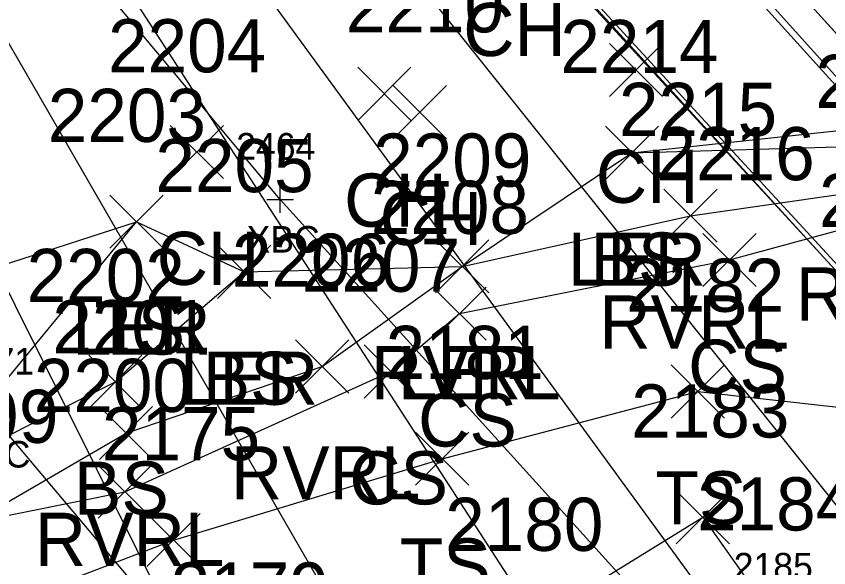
# Model space of a CAD drawing. Extents: x 1504228 to 1506103, y 437717 to 440106.
# Drawn here: x 1505234.96 to 1505265.52, y 438165.45 to 438186.2 of the extents above; entities that cross this region are included whole.
import ezdxf

# ---------------------------------------------------------------- set-up
doc = ezdxf.new("R2010")
doc.units = 0
for name, color, linetype in [('B_A', 7, 'Continuous'), ('B_I', 7, 'Continuous'), ('B_TIC', 7, 'Continuous'), ('BB', 7, 'Continuous'), ('BDC', 7, 'Continuous'), ('BELB', 7, 'Continuous'), ('BF', 7, 'Continuous'), ('BR', 7, 'Continuous'), ('L_A', 7, 'Continuous'), ('L_I', 7, 'Continuous'), ('L_TIC', 7, 'Continuous'), ('LARO', 7, 'Continuous'), ('LAWE', 7, 'Continuous'), ('LELB', 7, 'Continuous')]:
    doc.layers.add(name, color=color, linetype=linetype)

msp = doc.modelspace()

# ---------------------------------------------------------------- linework, layer by layer
at = {"layer": 'B_TIC'}
msp.add_line((1505244.887, 438179.311), (1505244.963, 438179.311), dxfattribs=at)
for points in [[(1505244.884, 438178.811), (1505244.884, 438179.811)], [(1505244.384, 438179.311), (1505245.384, 438179.311)]]:
    msp.add_lwpolyline(points, dxfattribs=at)
at = {"layer": 'BB'}
for points in [[(1505279.36, 438168.588), (1505247.631, 438203.673)], [(1505274.859, 438166.697), (1505243.111, 438201.465)], [(1505269.01, 438163.806), (1505239.92, 438200.195)], [(1505263.198, 438161.205), (1505236.12, 438198.358)], [(1505257.379, 438159.077), (1505232.798, 438197.013)], [(1505251.441, 438156.129), (1505228.857, 438195.264)], [(1505245.599, 438153.876), (1505225.746, 438193.733)]]:
    msp.add_lwpolyline(points, dxfattribs=at)
at = {"layer": 'BDC'}
msp.add_lwpolyline([(1505211.925, 438243.921), (1505227.096, 438222.88), (1505239.823, 438206.409), (1505253.849, 438189.887), (1505268.071, 438174.436), (1505276.686, 438165.513)], dxfattribs=at)
at = {"layer": 'BELB'}
for points in [[(1505211.812, 438243.704), (1505226.972, 438222.631), (1505239.63, 438206.209), (1505253.732, 438189.745), (1505267.938, 438174.29), (1505276.516, 438165.316)], [(1505262.808, 438159.474), (1505244.884, 438179.311), (1505229.042, 438198.247), (1505213.306, 438219.16), (1505200.113, 438237.757)], [(1505189.093, 438232.07), (1505202.074, 438213.317), (1505217.089, 438192.519), (1505234.002, 438171.224), (1505249.231, 438153.134)]]:
    msp.add_lwpolyline(points, dxfattribs=at)
at = {"layer": 'BF'}
for points in [[(1505211.925, 438243.921), (1505216.347, 438245.376), (1505218.618, 438242.78), (1505219.411, 438243.379), (1505231.883, 438226.243), (1505244.785, 438210.059), (1505258.149, 438194.034), (1505272.082, 438178.605), (1505279.641, 438170.867), (1505278.911, 438170.024), (1505281.091, 438167.856), (1505276.686, 438165.513)], [(1505219.325, 438243.288), (1505231.877, 438226.273), (1505244.695, 438209.964), (1505258.118, 438194.019), (1505272.126, 438178.595), (1505280.957, 438169.659)]]:
    msp.add_lwpolyline(points, dxfattribs=at)
at = {"layer": 'BR'}
msp.add_lwpolyline([(1505218.618, 438242.78), (1505231.125, 438225.649), (1505244.017, 438209.29), (1505257.36, 438193.318), (1505271.307, 438177.817), (1505278.911, 438170.024)], dxfattribs=at)
at = {"layer": 'L_TIC'}
for points in [[(1505257.268, 438183.183), (1505259.268, 438185.183)], [(1505259.268, 438183.183), (1505257.268, 438185.183)], [(1505247.799, 438182.285), (1505249.799, 438184.285)], [(1505249.799, 438182.285), (1505247.799, 438184.285)], [(1505249.135, 438181.597), (1505251.135, 438183.597)], [(1505251.135, 438181.597), (1505249.135, 438183.597)], [(1505240.748, 438180.094), (1505242.748, 438182.094)], [(1505242.748, 438180.094), (1505240.748, 438182.094)], [(1505257.116, 438180.066), (1505259.116, 438182.066)], [(1505259.116, 438180.066), (1505257.116, 438182.066)], [(1505257.116, 438180.066), (1505259.116, 438182.066)], [(1505259.116, 438180.066), (1505257.116, 438182.066)], [(1505259.319, 438177.7), (1505261.319, 438179.7)], [(1505261.319, 438177.7), (1505259.319, 438179.7)], [(1505238.482, 438177.474), (1505240.482, 438179.474)], [(1505240.482, 438177.474), (1505238.482, 438179.474)], [(1505238.482, 438177.474), (1505240.482, 438179.474)], [(1505240.482, 438177.474), (1505238.482, 438179.474)], [(1505260.788, 438176.035), (1505262.788, 438178.035)], [(1505262.788, 438176.035), (1505260.788, 438178.035)], [(1505250.729, 438175.792), (1505252.729, 438177.792)], [(1505252.729, 438175.792), (1505250.729, 438177.792)], [(1505250.729, 438175.792), (1505252.729, 438177.792)], [(1505252.729, 438175.792), (1505250.729, 438177.792)], [(1505242.528, 438175.585), (1505244.528, 438177.585)], [(1505244.528, 438175.585), (1505242.528, 438177.585)], [(1505242.528, 438175.585), (1505244.528, 438177.585)], [(1505244.528, 438175.585), (1505242.528, 438177.585)], [(1505250.629, 438174.015), (1505252.629, 438176.015)], [(1505252.629, 438174.015), (1505250.629, 438176.015)], [(1505245.461, 438172.024), (1505247.461, 438174.024)], [(1505247.461, 438172.024), (1505245.461, 438174.024)], [(1505248.04, 438171.836), (1505250.04, 438173.836)], [(1505250.04, 438171.836), (1505248.04, 438173.836)], [(1505237.686, 438171.451), (1505239.686, 438173.451)], [(1505239.686, 438171.451), (1505237.686, 438173.451)], [(1505259.591, 438171.084), (1505261.591, 438173.084)], [(1505261.591, 438171.084), (1505259.591, 438173.084)], [(1505238.085, 438169.522), (1505240.085, 438171.522)], [(1505240.085, 438169.522), (1505238.085, 438171.522)], [(1505249.977, 438168.557), (1505251.977, 438170.557)], [(1505251.977, 438168.557), (1505249.977, 438170.557)], [(1505238.043, 438167.314), (1505240.043, 438169.314)], [(1505240.043, 438167.314), (1505238.043, 438169.314)], [(1505259.782, 438166.353), (1505261.782, 438168.353)], [(1505261.782, 438166.353), (1505259.782, 438168.353)], [(1505239.87, 438165.496), (1505241.87, 438167.496)], [(1505241.87, 438165.496), (1505239.87, 438167.496)]]:
    msp.add_lwpolyline(points, dxfattribs=at)
at = {"layer": 'LARO'}
msp.add_lwpolyline([(1505225.066, 438161.326), (1505226.248, 438169.057), (1505228.34, 438173.672), (1505225.288, 438173.876), (1505239.482, 438178.474), (1505243.528, 438176.585), (1505251.729, 438176.792), (1505258.116, 438181.066), (1505273.159, 438181.503), (1505274.516, 438179.171), (1505287.419, 438180.921)], dxfattribs=at)
at = {"layer": 'LAWE'}
msp.add_lwpolyline([(1505191.715, 438146.002), (1505202.906, 438148.803), (1505214.791, 438151.569), (1505218.42, 438155.881), (1505225.066, 438161.326), (1505233.297, 438167.151), (1505239.085, 438170.522), (1505246.461, 438173.024), (1505251.729, 438176.792), (1505260.319, 438178.7), (1505267.708, 438179.756), (1505273.159, 438181.503), (1505280.716, 438184.584), (1505293.606, 438188.67), (1505306.287, 438194.997), (1505316.183, 438195.439), (1505329.815, 438205.572), (1505347.823, 438213.433)], dxfattribs=at)
at = {"layer": 'LELB'}
for points in [[(1505258.116, 438181.066), (1505268.339, 438182.172), (1505278.498, 438189.358), (1505293.602, 438192.608), (1505306.445, 438196.96), (1505314.273, 438197.344), (1505329.9, 438207.293), (1505346.396, 438216.217), (1505367.728, 438232.021), (1505378.412, 438248.378), (1505391.234, 438272.553), (1505398.951, 438287.599)], [(1505215.631, 438142.954), (1505216.782, 438152.684), (1505223.21, 438155.651), (1505231.417, 438162.88), (1505240.87, 438166.496), (1505250.977, 438169.557), (1505260.591, 438172.084), (1505271.035, 438170.915), (1505277.265, 438170.598), (1505281.518, 438175.58), (1505287.828, 438178.641), (1505292.056, 438179.708), (1505296.753, 438181.832), (1505306.221, 438188.545)], [(1505233.297, 438167.151), (1505239.043, 438168.314), (1505249.04, 438172.836), (1505251.629, 438175.015), (1505261.788, 438177.035), (1505269.325, 438179.089), (1505274.516, 438179.171), (1505268.419, 438175.277), (1505270.919, 438173.353), (1505279.4, 438176.776), (1505285.106, 438180.489)], [(1505231.587, 438168.903), (1505239.482, 438178.474)], [(1505226.248, 438169.057), (1505231.587, 438168.903), (1505238.686, 438172.451), (1505243.528, 438176.585)], [(1505245.889, 438156.33), (1505243.468, 438160.651), (1505253.871, 438163.088), (1505260.782, 438167.353), (1505263.257, 438163.856)]]:
    msp.add_lwpolyline(points, dxfattribs=at)

# ---------------------------------------------------------------- texts
at = {"layer": 'B_A'}
for p in [(1505243.62, 438177.311), (1505232.738, 438169.224)]:
    msp.add_text('XBC', height=1, dxfattribs=at).set_placement(p)
at = {"layer": 'B_I'}
for s, p in [('2464', (1505243.23, 438180.811)), ('2471', (1505232.655, 438172.724)), ('2185', (1505261.944, 438165.011))]:
    msp.add_text(s, height=1, dxfattribs=at).set_placement(p)
at = {"layer": 'L_A'}
for s, p in [('CH', (1505251.768, 438184.706)), ('CH', (1505256.756, 438179.183)), ('CH', (1505247.287, 438178.285)), ('CH', (1505248.623, 438177.597)), ('CH', (1505240.236, 438176.094)), ('LER', (1505255.698, 438176.066)), ('BS', (1505256.556, 438176.066)), ('RVRL', (1505264.275, 438174.756)), ('RVRL', (1505256.886, 438173.7)), ('LER', (1505237.064, 438173.474)), ('TS', (1505237.891, 438173.474)), ('CS', (1505260.229, 438172.035)), ('RVRL', (1505248.296, 438171.792)), ('LER', (1505249.312, 438171.792)), ('LER', (1505241.111, 438171.585)), ('BS', (1505241.969, 438171.585)), ('CS', (1505250.07, 438170.015)), ('RVRL', (1505243.028, 438168.024)), ('CS', (1505247.481, 438167.836)), ('BS', (1505237.127, 438167.451)), ('TS', (1505259.001, 438167.084)), ('RVRL', (1505235.652, 438165.522)), ('TS', (1505249.387, 438164.557))]:
    msp.add_text(s, height=2, dxfattribs=at).set_placement(p)
at = {"layer": 'L_I'}
for s, p in [('2210', (1505247.355, 438185.597)), ('2204', (1505238.409, 438184.094)), ('2214', (1505255.423, 438184.066)), ('2214', (1505255.423, 438184.066)), ('2218', (1505265.016, 438182.756)), ('2203', (1505236.143, 438181.474)), ('2203', (1505236.143, 438181.474)), ('2215', (1505257.626, 438181.7)), ('2216', (1505259.04, 438180.035)), ('2209', (1505248.383, 438179.792)), ('2209', (1505248.383, 438179.792)), ('2205', (1505240.19, 438179.585)), ('2205', (1505240.19, 438179.585)), ('2229', (1505265.151, 438178.277)), ('2208', (1505248.29, 438178.015)), ('2206', (1505243.067, 438176.024)), ('2207', (1505245.701, 438175.836)), ('2202', (1505235.347, 438175.451)), ('2182', (1505257.898, 438175.084)), ('2201', (1505236.313, 438173.522)), ('2181', (1505248.851, 438172.557)), ('2200', (1505235.618, 438171.314)), ('2199', (1505230.596, 438170.151)), ('2199', (1505230.596, 438170.151)), ('2183', (1505258.089, 438170.353)), ('2175', (1505238.178, 438169.496)), ('2184', (1505260.564, 438166.856)), ('2184', (1505260.564, 438166.856)), ('2180', (1505251.091, 438166.088)), ('2179', (1505240.767, 438163.651))]:
    msp.add_text(s, height=2, dxfattribs=at).set_placement(p)

doc.saveas('drawing.dxf')
